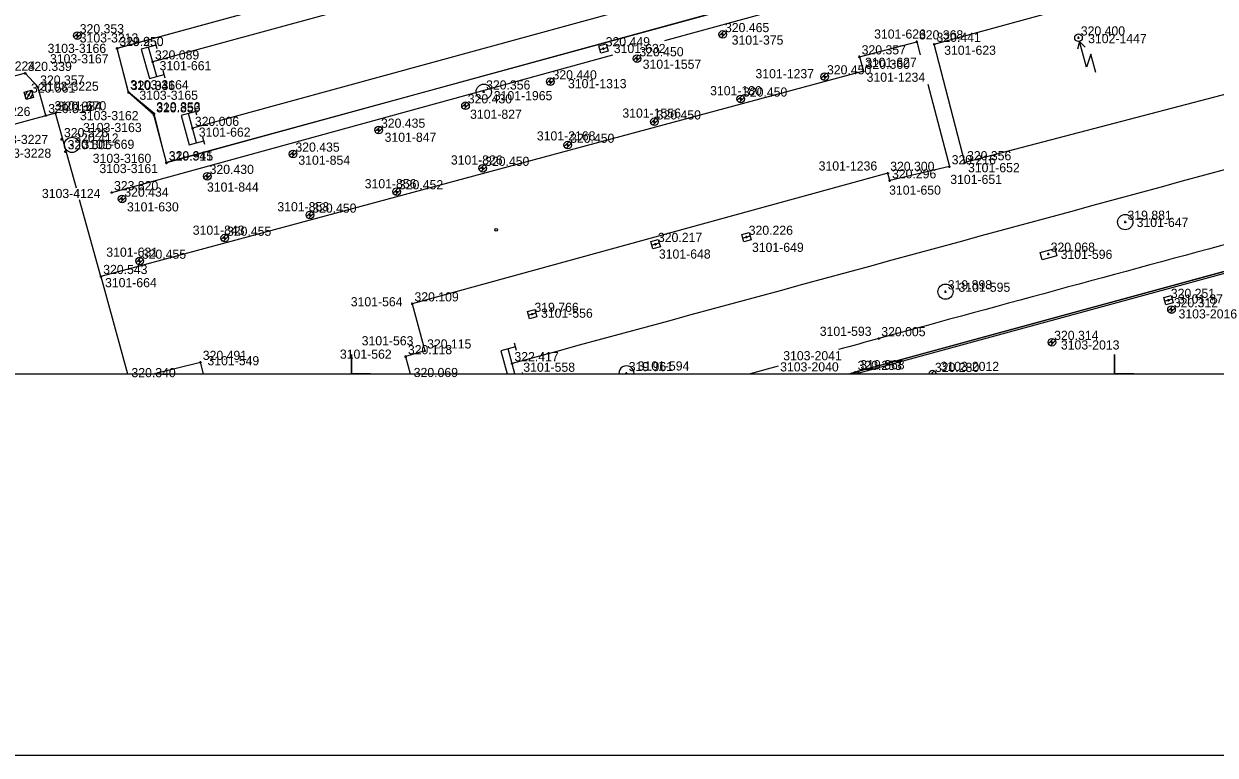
# Model space of a CAD drawing. Extents: x -821875 to -821475, y -1070280 to -1069975.
# Drawn here: x -821621.5 to -821543.4, y -1070275 to -1070227.1 of the extents above; entities that cross this region are included whole.
import ezdxf

# ---------------------------------------------------------------- set-up
doc = ezdxf.new("R2010")
doc.units = 0
for name, color, linetype in [('Vrstva 1', 7, 'Continuous'), ('Vrstva 11', 7, 'Continuous'), ('Vrstva 14', 7, 'Continuous'), ('Vrstva 15', 7, 'Continuous'), ('Vrstva 17', 7, 'Continuous'), ('Vrstva 23', 7, 'Continuous'), ('Vrstva 25', 7, 'Continuous'), ('Vrstva 3', 7, 'Continuous'), ('Vrstva 36', 7, 'Continuous'), ('Vrstva 43', 7, 'Continuous'), ('Vrstva 59', 7, 'Continuous'), ('Vrstva 60', 7, 'Continuous'), ('Vrstva 61', 7, 'Continuous')]:
    doc.layers.add(name, color=color, linetype=linetype)

# ---------------------------------------------------------------- blocks, each defined once
blk = doc.blocks.new('BOD')
at = {"layer": 'Vrstva 3'}
for p, q in [((-0.15, 0), (0.15, 0)), ((0, -0.15), (0, 0.15))]:
    blk.add_line(p, q, dxfattribs=at)

msp = doc.modelspace()

# ---------------------------------------------------------------- linework, layer by layer
at = {"layer": 'Vrstva 1'}
for p, q in [((-821588.818, -1070222.954), (-821613.034, -1070229.557)), ((-821568.932, -1070222.548), (-821610.421, -1070233.913)), ((-821572.051, -1070249.501), (-821573.875, -1070250))]:
    msp.add_line(p, q, dxfattribs=at)
for points in [[(-821475, -1069975), (-821875, -1069975), (-821875, -1070275), (-821475, -1070275)], [(-821500, -1070000), (-821850, -1070000), (-821850, -1070250), (-821500, -1070250)], [(-821500, -1070000), (-821850, -1070000), (-821850, -1070250), (-821500, -1070250)]]:
    msp.add_lwpolyline(points, close=True, dxfattribs=at)
for points in [[(-821600, -1070250), (-821600, -1070248.75), (-821600, -1070250)], [(-821550, -1070250), (-821550, -1070248.75), (-821550, -1070250)], [(-821601.25, -1070250), (-821600, -1070250)], [(-821600, -1070250), (-821598.75, -1070250), (-821600, -1070250)], [(-821551.25, -1070250), (-821550, -1070250)], [(-821550, -1070250), (-821548.75, -1070250), (-821550, -1070250)]]:
    msp.add_lwpolyline(points, dxfattribs=at)
for points in [[(-821500, -1070224.932), (-821542.652, -1070236.59), (-821589.48, -1070249.332)], [(-821528.375, -1070237.618), (-821540.754, -1070240.99), (-821565.441, -1070247.694), (-821568.087, -1070248.417)]]:
    msp.add_spline(points, degree=3, dxfattribs=at)
at = {"layer": 'Vrstva 11'}
for p, q in [((-821621.237, -1070231.492), (-821621.402, -1070231.782)), ((-821620.983, -1070231.424), (-821621.331, -1070232.036)), ((-821620.913, -1070231.679), (-821621.076, -1070231.966))]:
    msp.add_line(p, q, dxfattribs=at)
msp.add_lwpolyline([(-821620.851, -1070231.904), (-821621.333, -1070232.036), (-821621.465, -1070231.554), (-821620.983, -1070231.422)], close=True, dxfattribs=at)
msp.add_lwpolyline([(-821620.851, -1070231.904), (-821621.333, -1070232.036), (-821621.465, -1070231.554), (-821620.983, -1070231.422), (-821620.851, -1070231.904)], dxfattribs=at)
at = {"layer": 'Vrstva 14'}
for p, q in [((-821567.723, -1070224.034), (-821612.131, -1070236.166)), ((-821567.873, -1070224.036), (-821612.125, -1070236.188)), ((-821566.98, -1070250), (-821509.06, -1070234.242))]:
    msp.add_line(p, q, dxfattribs=at)
for points in [[(-821589.624, -1070221.624), (-821615.371, -1070228.68), (-821615.366, -1070228.674), (-821589.911, -1070221.714)], [(-821612.125, -1070236.188), (-821612.944, -1070232.956), (-821614.613, -1070231.556), (-821615.371, -1070228.68)], [(-821612.131, -1070236.166), (-821612.957, -1070233.026), (-821614.619, -1070231.562), (-821615.366, -1070228.674)], [(-821612.957, -1070233.026), (-821612.944, -1070232.956)], [(-821612.125, -1070236.188), (-821612.131, -1070236.166)], [(-821523.059, -1070237.903), (-821566.994, -1070249.906)], [(-821522.734, -1070237.84), (-821566.814, -1070249.862)], [(-821566.994, -1070249.906), (-821567.34, -1070250)], [(-821567.321, -1070250), (-821566.814, -1070249.862)]]:
    msp.add_lwpolyline(points, dxfattribs=at)
at = {"layer": 'Vrstva 15'}
for p, q in [((-821612.749, -1070228.702), (-821612.88, -1070228.219)), ((-821612.77, -1070230.522), (-821613.298, -1070228.592)), ((-821612.222, -1070230.632), (-821612.354, -1070230.149)), ((-821610.157, -1070234.877), (-821610.685, -1070232.949)), ((-821610.137, -1070233.058), (-821610.269, -1070232.576)), ((-821609.609, -1070234.986), (-821609.741, -1070234.504)), ((-821589.197, -1070248.476), (-821589.329, -1070247.994)), ((-821589.296, -1070250), (-821589.745, -1070248.368)), ((-821588.778, -1070250), (-821588.799, -1070249.922))]:
    msp.add_line(p, q, dxfattribs=at)
for points in [[(-821612.815, -1070228.46), (-821613.78, -1070228.724), (-821613.253, -1070230.654), (-821612.288, -1070230.39)], [(-821610.203, -1070232.817), (-821611.167, -1070233.081), (-821610.639, -1070235.009), (-821609.675, -1070234.745)], [(-821589.263, -1070248.236), (-821590.227, -1070248.501), (-821589.815, -1070250)]]:
    msp.add_lwpolyline(points, dxfattribs=at)
at = {"layer": 'Vrstva 17'}
for p, q in [((-821621.383, -1070230.309), (-821633.688, -1070233.585)), ((-821620.558, -1070231.203), (-821621.383, -1070230.309)), ((-821620.028, -1070233.073), (-821620.558, -1070231.203))]:
    msp.add_line(p, q, dxfattribs=at)
msp.add_lwpolyline([(-821561.818, -1070228.402), (-821540.931, -1070222.686), (-821538.779, -1070230.644), (-821559.821, -1070236.162), (-821561.818, -1070228.402)], dxfattribs=at)
at = {"layer": 'Vrstva 23'}
for points in [[(-821579.481, -1070228.171), (-821564.133, -1070223.955)], [(-821566.725, -1070229.225), (-821562.971, -1070228.242), (-821562.745, -1070229.104)], [(-821566.725, -1070229.225), (-821566.464, -1070230.17), (-821616.426, -1070243.62)], [(-821615.719, -1070238.125), (-821582.884, -1070229.106)], [(-821562.242, -1070231.026), (-821560.827, -1070236.429), (-821564.737, -1070237.349)], [(-821618.032, -1070237.847), (-821619.404, -1070232.915), (-821629.947, -1070235.793), (-821628.796, -1070240.434), (-821629.722, -1070241.929), (-821630.734, -1070242.226), (-821629.687, -1070246.101), (-821630.928, -1070246.466), (-821632.123, -1070248.555), (-821635.379, -1070249.449), (-821635.229, -1070250)], [(-821564.737, -1070237.349), (-821564.856, -1070236.858), (-821596.029, -1070245.413)], [(-821616.426, -1070243.62), (-821617.824, -1070238.596)], [(-821616.426, -1070243.62), (-821614.678, -1070250)], [(-821596.029, -1070245.413), (-821595.201, -1070248.498), (-821596.461, -1070248.874), (-821596.172, -1070250)], [(-821613.007, -1070250), (-821609.901, -1070249.249)], [(-821609.697, -1070250), (-821609.901, -1070249.249)]]:
    msp.add_lwpolyline(points, dxfattribs=at)
at = {"layer": 'Vrstva 25'}
for p, q in [((-821552.3, -1070228.225), (-821552.422, -1070228.725)), ((-821552.342, -1070227.978), (-821552.39, -1070227.99)), ((-821551.838, -1070229.913), (-821552.3, -1070228.225)), ((-821551.94, -1070228.593), (-821552.3, -1070228.225)), ((-821551.554, -1070229.057), (-821551.838, -1070229.913)), ((-821551.224, -1070230.263), (-821551.554, -1070229.057))]:
    msp.add_line(p, q, dxfattribs=at)
msp.add_lwpolyline([(-821553.92, -1070241.785), (-821553.79, -1070242.268), (-821554.756, -1070242.529), (-821554.886, -1070242.046), (-821553.92, -1070241.785)], dxfattribs=at)
msp.add_circle((-821552.366, -1070227.984), 0.25, dxfattribs=at)
at = {"layer": 'Vrstva 36'}
for p, q in [((-821618.194, -1070227.936), (-821617.872, -1070227.613)), ((-821618.064, -1070228.071), (-821617.737, -1070227.744)), ((-821575.912, -1070227.858), (-821575.588, -1070227.535)), ((-821575.782, -1070227.993), (-821575.454, -1070227.666)), ((-821581.524, -1070229.442), (-821581.2, -1070229.119)), ((-821581.394, -1070229.577), (-821581.066, -1070229.25)), ((-821587.212, -1070230.953), (-821586.89, -1070230.63)), ((-821587.082, -1070231.088), (-821586.755, -1070230.76)), ((-821569.228, -1070230.624), (-821568.904, -1070230.301)), ((-821569.098, -1070230.759), (-821568.77, -1070230.432)), ((-821592.766, -1070232.528), (-821592.444, -1070232.205)), ((-821592.636, -1070232.663), (-821592.309, -1070232.336)), ((-821574.73, -1070232.082), (-821574.406, -1070231.759)), ((-821574.6, -1070232.217), (-821574.272, -1070231.89)), ((-821598.454, -1070234.123), (-821598.132, -1070233.8)), ((-821598.324, -1070234.258), (-821597.997, -1070233.93)), ((-821580.386, -1070233.58), (-821580.064, -1070233.257)), ((-821580.256, -1070233.715), (-821579.929, -1070233.388)), ((-821586.062, -1070235.11), (-821585.738, -1070234.787)), ((-821604.062, -1070235.692), (-821603.74, -1070235.369)), ((-821603.932, -1070235.827), (-821603.605, -1070235.5)), ((-821585.932, -1070235.245), (-821585.604, -1070234.918)), ((-821591.632, -1070236.624), (-821591.31, -1070236.301)), ((-821609.684, -1070237.15), (-821609.36, -1070236.827)), ((-821609.554, -1070237.285), (-821609.226, -1070236.958)), ((-821591.502, -1070236.759), (-821591.175, -1070236.432)), ((-821597.278, -1070238.158), (-821596.954, -1070237.835)), ((-821615.272, -1070238.64), (-821614.948, -1070238.317)), ((-821615.142, -1070238.775), (-821614.814, -1070238.448)), ((-821597.148, -1070238.293), (-821596.82, -1070237.966)), ((-821602.958, -1070239.69), (-821602.636, -1070239.367)), ((-821602.828, -1070239.825), (-821602.501, -1070239.498)), ((-821608.544, -1070241.204), (-821608.22, -1070240.881)), ((-821608.414, -1070241.339), (-821608.086, -1070241.012)), ((-821614.124, -1070242.709), (-821613.8, -1070242.386)), ((-821613.994, -1070242.844), (-821613.666, -1070242.516)), ((-821546.502, -1070245.891), (-821546.18, -1070245.568)), ((-821546.372, -1070246.026), (-821546.045, -1070245.698)), ((-821554.342, -1070248.03), (-821554.02, -1070247.707)), ((-821554.212, -1070248.165), (-821553.885, -1070247.838)), ((-821562.029, -1070250), (-821561.834, -1070249.804)), ((-821561.765, -1070250), (-821561.699, -1070249.934))]:
    msp.add_line(p, q, dxfattribs=at)
for centre in [(-821617.964, -1070227.844), (-821575.681, -1070227.766), (-821581.293, -1070229.35), (-821586.982, -1070230.861), (-821568.997, -1070230.532), (-821592.536, -1070232.436), (-821574.499, -1070231.99), (-821580.156, -1070233.488), (-821598.224, -1070234.031), (-821585.831, -1070235.018), (-821603.832, -1070235.6), (-821591.402, -1070236.532), (-821609.453, -1070237.058), (-821597.047, -1070238.066), (-821615.041, -1070238.548), (-821602.728, -1070239.598), (-821608.313, -1070241.112), (-821613.893, -1070242.617), (-821546.272, -1070245.799), (-821554.112, -1070247.938)]:
    msp.add_circle(centre, 0.25, dxfattribs=at)
msp.add_arc((-821561.926, -1070250.035), 0.25, 8.04785, 171.95216, dxfattribs=at)
at = {"layer": 'Vrstva 43'}
for points in [[(-821583.741, -1070228.758), (-821583.805, -1070228.516), (-821583.321, -1070228.388), (-821583.193, -1070228.872), (-821583.677, -1070229), (-821583.741, -1070228.758), (-821583.257, -1070228.63)], [(-821573.887, -1070240.982), (-821573.821, -1070241.223), (-821574.303, -1070241.355), (-821574.435, -1070240.873), (-821573.953, -1070240.741), (-821573.887, -1070240.982), (-821574.369, -1070241.114)], [(-821579.834, -1070241.451), (-821579.768, -1070241.692), (-821580.25, -1070241.824), (-821580.382, -1070241.342), (-821579.9, -1070241.21), (-821579.834, -1070241.451), (-821580.316, -1070241.583)], [(-821546.225, -1070245.118), (-821546.16, -1070245.359), (-821546.642, -1070245.489), (-821546.772, -1070245.007), (-821546.29, -1070244.877), (-821546.225, -1070245.118), (-821546.707, -1070245.248)], [(-821587.926, -1070246.032), (-821587.86, -1070246.273), (-821588.342, -1070246.405), (-821588.474, -1070245.923), (-821587.992, -1070245.791), (-821587.926, -1070246.032), (-821588.408, -1070246.164)]]:
    msp.add_lwpolyline(points, dxfattribs=at)
for centre in [(-821591.336, -1070231.525), (-821618.319, -1070235.007), (-821549.305, -1070240.063), (-821561.082, -1070244.624)]:
    msp.add_circle(centre, 0.5, dxfattribs=at)
msp.add_arc((-821581.988, -1070249.983), 0.5, 358.05157, 181.94843, dxfattribs=at)
at = {"layer": 'Vrstva 59'}
msp.add_circle((-821590.523, -1070240.578), 0.0873, dxfattribs=at)
at = {"layer": 'Vrstva 60'}
for p, q in [((-821582.063, -1070249.983), (-821581.913, -1070249.983)), ((-821581.988, -1070250), (-821581.988, -1070249.908)), ((-821561.926, -1070250), (-821561.926, -1070249.96))]:
    msp.add_line(p, q, dxfattribs=at)

# ---------------------------------------------------------------- block references
at = {"layer": 'Vrstva 60', "xscale": 0.5, "yscale": 0.5}
for p in [(-821617.964, -1070227.844), (-821575.681, -1070227.766), (-821562.971, -1070228.242), (-821561.818, -1070228.402), (-821552.366, -1070227.984), (-821615.371, -1070228.68), (-821615.366, -1070228.674), (-821583.499, -1070228.694), (-821581.293, -1070229.35), (-821566.725, -1070229.225), (-821613.034, -1070229.557), (-821566.464, -1070230.17), (-821621.383, -1070230.309), (-821586.982, -1070230.861), (-821568.997, -1070230.532), (-821621.158, -1070231.729), (-821620.558, -1070231.203), (-821614.619, -1070231.562), (-821614.613, -1070231.556), (-821591.336, -1070231.525), (-821592.536, -1070232.436), (-821574.499, -1070231.99), (-821620.028, -1070233.073), (-821619.404, -1070232.915), (-821612.957, -1070233.026), (-821612.944, -1070232.956), (-821610.421, -1070233.913), (-821598.224, -1070234.031), (-821580.156, -1070233.488), (-821618.999, -1070234.648), (-821618.757, -1070235.441), (-821618.319, -1070235.007), (-821603.832, -1070235.6), (-821585.831, -1070235.018), (-821612.131, -1070236.166), (-821612.125, -1070236.188), (-821560.827, -1070236.429), (-821559.821, -1070236.162), (-821609.453, -1070237.058), (-821591.402, -1070236.532), (-821564.856, -1070236.858), (-821564.737, -1070237.349), (-821615.719, -1070238.125), (-821615.041, -1070238.548), (-821597.047, -1070238.066), (-821602.728, -1070239.598), (-821549.305, -1070240.063), (-821608.313, -1070241.112), (-821574.128, -1070241.048), (-821580.075, -1070241.517), (-821613.893, -1070242.617), (-821554.338, -1070242.157), (-821616.426, -1070243.62), (-821561.082, -1070244.624), (-821596.029, -1070245.413), (-821546.466, -1070245.183), (-821546.272, -1070245.799), (-821588.167, -1070246.098), (-821565.441, -1070247.694), (-821554.112, -1070247.938), (-821596.461, -1070248.874), (-821595.201, -1070248.498), (-821609.901, -1070249.249), (-821589.48, -1070249.332), (-821566.994, -1070249.906), (-821566.814, -1070249.862)]:
    msp.add_blockref('BOD', p, dxfattribs=at)

# ---------------------------------------------------------------- texts
at = {"layer": 'Vrstva 60'}
for s, p in [('3103-3213', (-821617.814, -1070228.294)), ('3101-626', (-821565.759, -1070228.037)), ('3102-1447', (-821551.735, -1070228.338)), ('3103-3166', (-821619.921, -1070228.979)), ('3101-632', (-821582.817, -1070228.988)), ('3101-375', (-821575.094, -1070228.435)), ('3101-623', (-821561.168, -1070229.102)), ('3103-3167', (-821619.765, -1070229.662)), ('3101-627', (-821566.356, -1070229.894)), ('3103-3224', (-821624.575, -1070230.134)), ('3101-661', (-821612.582, -1070230.114)), ('3101-1557', (-821580.924, -1070230.018)), ('3101-1237', (-821573.536, -1070230.638)), ('3103-3225', (-821620.408, -1070231.459)), ('3103-3164', (-821614.512, -1070231.365)), ('3101-1313', (-821585.819, -1070231.29)), ('3101-1234', (-821566.251, -1070230.87)), ('3103-3165', (-821613.903, -1070232.05)), ('3101-1965', (-821590.68, -1070232.076)), ('3101-180', (-821576.506, -1070231.753)), ('3101-670', (-821619.469, -1070232.741)), ('3103-3226', (-821624.881, -1070233.113)), ('3103-3162', (-821617.797, -1070233.385)), ('3101-827', (-821592.235, -1070233.295)), ('3101-1556', (-821582.256, -1070233.22)), ('3103-3163', (-821617.593, -1070234.165)), ('3101-662', (-821610.012, -1070234.47)), ('3103-3227', (-821623.722, -1070234.947)), ('3101-669', (-821617.63, -1070235.263)), ('3101-847', (-821597.836, -1070234.804)), ('3101-2168', (-821587.859, -1070234.714)), ('3103-3228', (-821623.523, -1070235.848)), ('3103-3160', (-821616.962, -1070236.186)), ('3103-3161', (-821616.524, -1070236.853)), ('3101-854', (-821603.488, -1070236.308)), ('3101-826', (-821593.494, -1070236.293)), ('3101-1236', (-821569.394, -1070236.683)), ('3101-652', (-821559.608, -1070236.799)), ('3101-651', (-821560.771, -1070237.566)), ('3103-4124', (-821620.291, -1070238.489)), ('3101-844', (-821609.476, -1070238.068)), ('3101-856', (-821599.14, -1070237.849)), ('3101-650', (-821564.775, -1070238.268)), ('3101-630', (-821614.718, -1070239.365)), ('3101-853', (-821604.863, -1070239.358)), ('3101-647', (-821548.558, -1070240.383)), ('3101-843', (-821610.406, -1070240.894)), ('3101-631', (-821616.072, -1070242.335)), ('3101-649', (-821573.763, -1070242.019)), ('3101-648', (-821579.863, -1070242.457)), ('3101-596', (-821553.538, -1070242.477)), ('3101-664', (-821616.157, -1070244.332)), ('3101-595', (-821560.23, -1070244.633)), ('3101-87', (-821545.848, -1070245.399)), ('3101-564', (-821600.054, -1070245.585)), ('3101-556', (-821587.588, -1070246.333)), ('3103-2016', (-821545.81, -1070246.379)), ('3101-593', (-821569.321, -1070247.521)), ('3101-563', (-821599.338, -1070248.142)), ('3103-2013', (-821553.52, -1070248.414)), ('3101-549', (-821609.445, -1070249.449)), ('3101-562', (-821600.765, -1070249.018)), ('3103-2041', (-821571.714, -1070249.12)), ('3101-558', (-821588.747, -1070249.874)), ('3101-594', (-821581.255, -1070249.79)), ('3103-2040', (-821571.917, -1070249.852)), ('3103-2012', (-821561.409, -1070249.821))]:
    msp.add_text(s, height=0.6, dxfattribs=at).set_placement(p)
at = {"layer": 'Vrstva 61'}
for s, p in [('320.353', (-821617.814, -1070227.694)), ('320.465', (-821575.531, -1070227.616)), ('320.368', (-821562.821, -1070228.092)), ('320.441', (-821561.668, -1070228.252)), ('320.400', (-821552.216, -1070227.834)), ('319.950', (-821615.221, -1070228.53)), ('320.250', (-821615.216, -1070228.524)), ('320.449', (-821583.349, -1070228.544)), ('320.357', (-821566.575, -1070229.075)), ('320.089', (-821612.884, -1070229.407)), ('320.450', (-821581.143, -1070229.2)), ('320.339', (-821621.233, -1070230.159)), ('320.440', (-821586.832, -1070230.711)), ('320.450', (-821568.847, -1070230.382)), ('320.360', (-821566.314, -1070230.02)), ('320.357', (-821620.408, -1070231.053)), ('320.345', (-821614.469, -1070231.412)), ('320.036', (-821614.463, -1070231.406)), ('320.356', (-821591.186, -1070231.375)), ('320.561', (-821621.008, -1070231.579)), ('320.430', (-821592.386, -1070232.286)), ('320.450', (-821574.349, -1070231.84)), ('320.314', (-821619.878, -1070232.923)), ('320.334', (-821619.254, -1070232.765)), ('320.359', (-821612.807, -1070232.876)), ('319.853', (-821612.794, -1070232.806)), ('320.006', (-821610.271, -1070233.763)), ('320.450', (-821580.006, -1070233.338)), ('320.526', (-821618.849, -1070234.498)), ('320.435', (-821598.074, -1070233.881)), ('320.505', (-821618.607, -1070235.291)), ('320.412', (-821618.169, -1070234.857)), ('320.450', (-821585.681, -1070234.868)), ('320.341', (-821611.981, -1070236.016)), ('319.915', (-821611.975, -1070236.038)), ('320.435', (-821603.682, -1070235.45)), ('320.356', (-821559.671, -1070236.012)), ('320.430', (-821609.303, -1070236.908)), ('320.450', (-821591.252, -1070236.382)), ('320.300', (-821564.706, -1070236.708)), ('320.216', (-821560.677, -1070236.279)), ('320.296', (-821564.587, -1070237.199)), ('323.820', (-821615.569, -1070237.975)), ('320.434', (-821614.891, -1070238.398)), ('320.452', (-821596.897, -1070237.916)), ('320.450', (-821602.578, -1070239.448)), ('319.881', (-821549.155, -1070239.913)), ('320.455', (-821608.163, -1070240.962)), ('320.217', (-821579.925, -1070241.367)), ('320.226', (-821573.978, -1070240.898)), ('320.068', (-821554.188, -1070242.007)), ('320.455', (-821613.743, -1070242.467)), ('320.543', (-821616.276, -1070243.47)), ('319.898', (-821560.932, -1070244.474)), ('320.109', (-821595.879, -1070245.263)), ('320.251', (-821546.316, -1070245.033)), ('319.766', (-821588.017, -1070245.948)), ('320.312', (-821546.122, -1070245.649)), ('320.005', (-821565.291, -1070247.544)), ('320.314', (-821553.962, -1070247.788)), ('320.115', (-821595.051, -1070248.348)), ('320.491', (-821609.751, -1070249.099)), ('320.118', (-821596.311, -1070248.724)), ('322.417', (-821589.33, -1070249.182)), ('320.340', (-821614.424, -1070250.229)), ('320.069', (-821595.927, -1070250.221)), ('319.961', (-821581.838, -1070249.833)), ('320.253', (-821566.844, -1070249.756)), ('319.868', (-821566.664, -1070249.712)), ('320.280', (-821561.776, -1070249.885))]:
    msp.add_text(s, height=0.6, dxfattribs=at).set_placement(p)

doc.saveas('drawing.dxf')
